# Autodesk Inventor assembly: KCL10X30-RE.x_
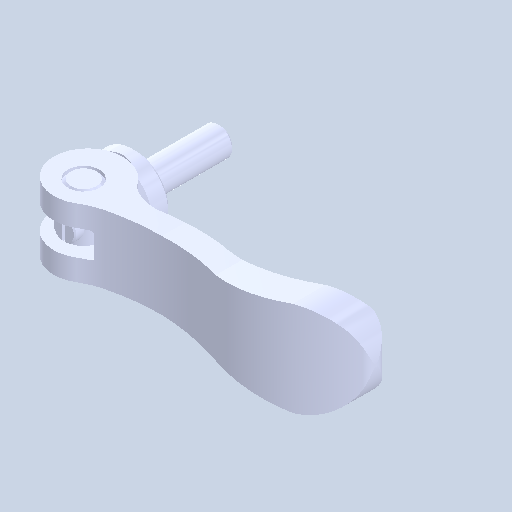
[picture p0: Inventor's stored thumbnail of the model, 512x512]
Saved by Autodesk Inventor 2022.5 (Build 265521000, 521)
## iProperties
Created: 2024-08
Part Number: KCL10X30-RE.x_
Document SubType Name: Assembly
Designer: ImaoCorp
Author: ImaoCorp
Sending System: SOLIDWORKS 2022-2022290
MC: AMD64
MC_MODEL: Intel64 Family 6 Model 60 Stepping 3, GenuineIntel
OS: Windows_NT
FRU: Parasolid Version 33.1, build 260,  4-25-2022
FORMAT: text
GUISE: transmit
KEY: FILEKCL10X30-RE.x_t
DATE: Thu Aug 29 10:50:59 2024
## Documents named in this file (5)
- Y:\5.更新分\2024年対応\1001_KCL\データ\kcl10x30-re\KCL10X30-RE.x_.iam
- Y:\5.更新分\2024年対応\1001_KCL\データ\kcl10x30-re\KCL10X30-RE_01.ipt
- Y:\5.更新分\2024年対応\1001_KCL\データ\kcl10x30-re\KCL10X30-RE_02.ipt
- Y:\5.更新分\2024年対応\1001_KCL\データ\kcl10x30-re\KCL10X30-RE_03.ipt
- Y:\5.更新分\2024年対応\1001_KCL\データ\kcl10x30-re\KCL10X30-RE_04.ipt
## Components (4 placed, 4 different names)
1. KCL10X30-RE_01
2. KCL10X30-RE_02
3. KCL10X30-RE_03
4. KCL10X30-RE_04
